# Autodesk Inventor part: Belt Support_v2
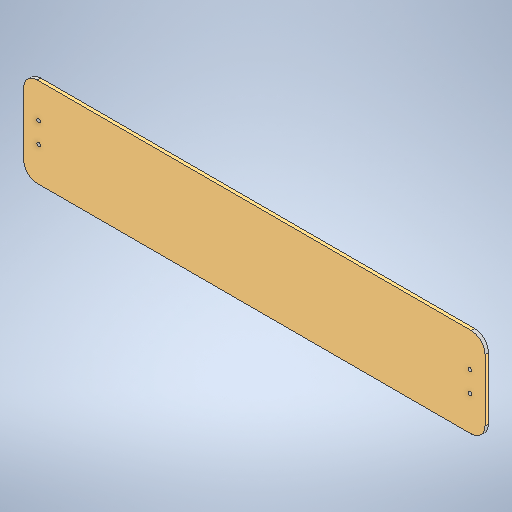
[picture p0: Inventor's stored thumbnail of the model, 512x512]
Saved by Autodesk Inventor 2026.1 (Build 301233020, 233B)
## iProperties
Created: 2026-10
Part Number: Belt Support_v2
Material: Generic
Document SubType Name: Modeling
Designer: hp
Density: 1 g/cm^3
Appearance: Default
Author: hp
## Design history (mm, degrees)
sketch "Sketch1"
  geometry: L1 (0, 0)-(670, 0); L2 (670, 0)-(670, 130); L3 (670, 130)-(0, 130); L4 (0, 130)-(0, 0)
  constraints: 8 end point, 2 parallel, 1 horizontal, 1 perpendicular
  dimensions: "d0" = 670 distance of L3.end L2.end; "d1" = 130 distance of L2.end L1.end
extrude "Extrusion1" new body sketch "Sketch1" distance "d2" = 5; taper "d3" = 0 deg
fillet "Fillet1" dims "d4" = 20
sketch "Sketch2"
  geometry: 4 further points
hole "Hole1" sketch "Sketch2" at (648, 50), (648, 80), (22, 50), (22, 80) diameter "d5" = 5.5; stored, may be unused: countersink angle "d9" = 90 deg, drill point angle "d11" = 0 deg; dims "d6" = 6, "d7" = 4, "d8" = 2, "d10" = 8
body "Solid1"
